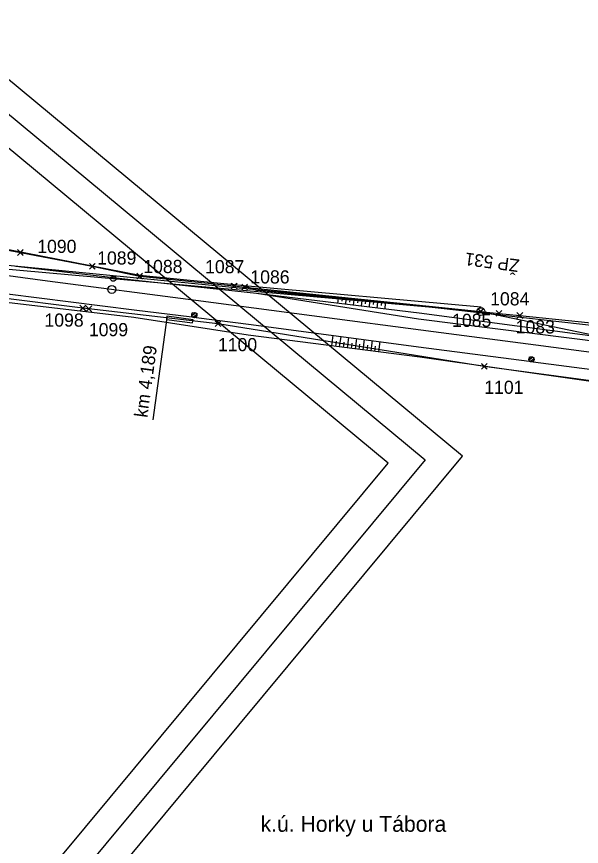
# Model space of a CAD drawing. Extents: x -738085 to -734426, y -1122197 to -1119748.
# Drawn here: x -737308.7 to -737201.5, y -1121531.4 to -1121373.8 of the extents above; entities that cross this region are included whole.
import ezdxf

# ---------------------------------------------------------------- set-up
doc = ezdxf.new("R2010")
doc.units = 0
for name, color, linetype in [('Polygon ku', 7, 'Continuous'), ('SŽDC', 7, 'Continuous'), ('Vrstva 1', 7, 'Continuous'), ('Vrstva 11', 7, 'Continuous'), ('Vrstva 12', 7, 'Continuous'), ('Vrstva 17', 7, 'Continuous'), ('Vrstva 48', 7, 'Continuous'), ('Vrstva 49', 7, 'Continuous'), ('Vrstva 60', 7, 'Continuous'), ('Vrstva 63', 7, 'Continuous'), ('Vrstva 7', 7, 'Continuous'), ('Vrstva 9', 7, 'Continuous')]:
    doc.layers.add(name, color=color, linetype=linetype)

msp = doc.modelspace()

# ---------------------------------------------------------------- linework, layer by layer
at = {"layer": 'SŽDC'}
for p, q in [((-737323.47, -1121415.6), (-737307.99, -1121418.58)), ((-737267.42, -1121424.92), (-737265.43, -1121425.13)), ((-737265.43, -1121425.13), (-737220.65, -1121429.77)), ((-737296.15, -1121429.13), (-737320.53, -1121426.11)), ((-737220.65, -1121429.77), (-737217.17, -1121430.13)), ((-737217.17, -1121430.13), (-737213.23, -1121430.54)), ((-737213.23, -1121430.54), (-737181.26, -1121433.89)), ((-737187.01, -1121444.71), (-737219.97, -1121440.21))]:
    msp.add_line(p, q, dxfattribs=at)
for points in [[(-737307.99, -1121418.58), (-737294.35, -1121421.2), (-737285.34, -1121423.08), (-737267.42, -1121424.92)], [(-737219.97, -1121440.21), (-737270.5, -1121432.11), (-737294.99, -1121429.27), (-737296.15, -1121429.13)]]:
    msp.add_lwpolyline(points, dxfattribs=at)
at = {"layer": 'Vrstva 1'}
for points in [[(-737452.56, -1121267.51), (-737989.34, -1121913.61), (-737760.91, -1122103.4), (-737224.12, -1121457.29)], [(-737982.3, -1121912.96), (-737451.91, -1121274.55), (-737231.17, -1121457.94), (-737761.56, -1122096.35)], [(-737451.26, -1121281.58), (-737844.27, -1121754.63), (-737631.21, -1121931.64), (-737238.2, -1121458.59)]]:
    msp.add_lwpolyline(points, close=True, dxfattribs=at)
msp.add_lwpolyline([(-737183.78, -1121439.67), (-737210.21, -1121436.2), (-737229.58, -1121433.65), (-737252.71, -1121430.59), (-737274.7, -1121427.68), (-737302.82, -1121423.99), (-737322.07, -1121421.44)], dxfattribs=at)
msp.add_lwpolyline([(-737183.78, -1121439.67), (-737210.21, -1121436.2), (-737229.58, -1121433.65), (-737252.71, -1121430.59), (-737274.7, -1121427.68), (-737302.82, -1121423.99), (-737322.07, -1121421.44)], dxfattribs=at)
at = {"layer": 'Vrstva 11'}
for p, q in [((-737274.72, -1121430.04), (-737275.46, -1121430.61)), ((-737274.5, -1121430.35), (-737275.22, -1121430.9)), ((-737210.75, -1121438.44), (-737211.49, -1121439.01)), ((-737210.53, -1121438.75), (-737211.26, -1121439.3))]:
    msp.add_line(p, q, dxfattribs=at)
for centre in [(-737274.98, -1121430.47), (-737211.01, -1121438.87)]:
    msp.add_circle(centre, 0.5, dxfattribs=at)
at = {"layer": 'Vrstva 12'}
for p, q in [((-737275.45, -1121430.82), (-737275.34, -1121430)), ((-737274.62, -1121430.93), (-737274.51, -1121430.11)), ((-737210.67, -1121439.32), (-737211.46, -1121439.21))]:
    msp.add_line(p, q, dxfattribs=at)
for points in [[(-737275.34, -1121430), (-737274.51, -1121430.11), (-737274.62, -1121430.93), (-737275.45, -1121430.82), (-737275.34, -1121430)], [(-737275.45, -1121430.82), (-737275.45, -1121430.82), (-737274.62, -1121430.93), (-737274.62, -1121430.93)], [(-737211.36, -1121438.42), (-737210.56, -1121438.52), (-737210.67, -1121439.32), (-737211.46, -1121439.21), (-737211.36, -1121438.42)], [(-737211.46, -1121439.21), (-737211.46, -1121439.21), (-737211.36, -1121438.42)], [(-737210.67, -1121439.32), (-737210.67, -1121439.32), (-737210.56, -1121438.52)]]:
    msp.add_lwpolyline(points, dxfattribs=at)
at = {"layer": 'Vrstva 17'}
msp.add_lwpolyline([(-737220.55, -1121428.94), (-737265.55, -1121424.89), (-737285.35, -1121422.95), (-737310.2, -1121418.09), (-737323.49, -1121415.48), (-737336.39, -1121414.26)], dxfattribs=at)
at = {"layer": 'Vrstva 48'}
for p, q in [((-737247.71, -1121427.28), (-737247.8, -1121428.23)), ((-737246.96, -1121427.35), (-737247.01, -1121427.83)), ((-737246.22, -1121427.42), (-737246.31, -1121428.41)), ((-737245.47, -1121427.5), (-737245.52, -1121428)), ((-737244.72, -1121427.57), (-737244.82, -1121428.59)), ((-737243.98, -1121427.64), (-737244.03, -1121428.16)), ((-737243.23, -1121427.71), (-737243.33, -1121428.77)), ((-737242.48, -1121427.78), (-737242.54, -1121428.32)), ((-737241.74, -1121427.86), (-737241.84, -1121428.95)), ((-737240.99, -1121427.93), (-737241.05, -1121428.48)), ((-737240.24, -1121428), (-737240.35, -1121429.13)), ((-737239.5, -1121428.07), (-737239.55, -1121428.65)), ((-737238.75, -1121428.14), (-737238.86, -1121429.31)), ((-737248.89, -1121436.3), (-737248.64, -1121434.3)), ((-737247.41, -1121436.49), (-737247.15, -1121434.5)), ((-737245.92, -1121436.68), (-737245.67, -1121434.7)), ((-737248.15, -1121436.4), (-737248.02, -1121435.4)), ((-737246.66, -1121436.59), (-737246.54, -1121435.59)), ((-737245.17, -1121436.78), (-737245.05, -1121435.79)), ((-737244.43, -1121436.87), (-737244.18, -1121434.9)), ((-737243.69, -1121436.97), (-737243.56, -1121435.98)), ((-737242.94, -1121437.06), (-737242.69, -1121435.1)), ((-737242.2, -1121437.16), (-737242.07, -1121436.18)), ((-737241.45, -1121437.25), (-737241.2, -1121435.3)), ((-737239.97, -1121437.44), (-737239.72, -1121435.5)), ((-737240.71, -1121437.35), (-737240.59, -1121436.37))]:
    msp.add_line(p, q, dxfattribs=at)
at = {"layer": 'Vrstva 49'}
msp.add_line((-737285.47, -1121423.95), (-737308.87, -1121421.25), dxfattribs=at)
for points in [[(-737285.35, -1121422.95), (-737310.2, -1121418.09), (-737316.73, -1121418.08), (-737334.06, -1121415.76)], [(-737080.08, -1121461.77), (-737090.67, -1121456.58), (-737111.11, -1121448.15), (-737130.72, -1121443.8), (-737153.05, -1121439.07), (-737181.79, -1121434.47), (-737232.07, -1121428.79), (-737263.11, -1121425.79), (-737265.55, -1121424.89), (-737285.35, -1121422.95)], [(-737042.34, -1121476.89), (-737045.96, -1121478.25), (-737051.31, -1121475.87), (-737059.65, -1121471.27), (-737080.08, -1121461.77), (-737095, -1121456.37), (-737113.75, -1121449.99), (-737130.88, -1121445.35), (-737152.07, -1121440.92), (-737182.74, -1121436.67), (-737232.31, -1121430.11), (-737263.17, -1121426.36), (-737285.47, -1121423.95)], [(-737310.42, -1121426.45), (-737286.42, -1121429.49), (-737275.45, -1121430.82), (-737274.62, -1121430.93), (-737264.2, -1121432.22), (-737232.43, -1121436.47), (-737211.46, -1121439.21), (-737210.67, -1121439.32), (-737183.93, -1121442.81), (-737153.07, -1121447.16), (-737152.28, -1121447.28), (-737151.31, -1121447.32), (-737132.33, -1121451.66), (-737115.31, -1121456.24), (-737098.74, -1121461.42), (-737083.52, -1121467.94), (-737082.8, -1121468.28), (-737082.23, -1121468.54), (-737062.89, -1121477.93), (-737046.92, -1121487.27), (-737045.25, -1121485.97)], [(-737044.27, -1121482.58), (-737060.3, -1121472.63), (-737080.61, -1121463.09), (-737095.26, -1121457.2), (-737114.01, -1121450.88), (-737131.11, -1121446.1), (-737152.37, -1121441.79), (-737182.77, -1121437.5), (-737232.42, -1121431.25), (-737263.17, -1121426.36)], [(-737045.25, -1121485.97), (-737046.65, -1121488.98), (-737063.8, -1121479.29), (-737083.11, -1121469.63), (-737099.88, -1121463.72), (-737115.42, -1121458.07), (-737133.05, -1121454.14), (-737151.03, -1121450.6), (-737184.2, -1121445.28), (-737232.18, -1121438.43), (-737264.79, -1121434.28), (-737286.45, -1121430.89), (-737310.61, -1121428.1)]]:
    msp.add_lwpolyline(points, dxfattribs=at)
at = {"layer": 'Vrstva 60'}
for p, q in [((-737307.54, -1121419.03), (-737308.54, -1121418.03)), ((-737307.54, -1121418.13), (-737308.54, -1121419.13)), ((-737308.44, -1121419.03), (-737307.44, -1121418.03)), ((-737308.44, -1121418.13), (-737307.44, -1121419.13)), ((-737307.99, -1121418.58), (-737307.99, -1121418.58)), ((-737293.9, -1121421.65), (-737294.9, -1121420.65)), ((-737293.9, -1121420.75), (-737294.9, -1121421.75)), ((-737294.8, -1121421.65), (-737293.8, -1121420.65)), ((-737294.8, -1121420.75), (-737293.8, -1121421.75)), ((-737294.35, -1121421.2), (-737294.35, -1121421.2)), ((-737284.89, -1121423.53), (-737285.89, -1121422.53)), ((-737284.89, -1121422.63), (-737285.89, -1121423.63)), ((-737285.79, -1121423.53), (-737284.79, -1121422.53)), ((-737285.79, -1121422.63), (-737284.79, -1121423.63)), ((-737285.34, -1121423.08), (-737285.34, -1121423.08)), ((-737266.97, -1121425.37), (-737267.97, -1121424.37)), ((-737266.97, -1121424.47), (-737267.97, -1121425.47)), ((-737267.87, -1121425.37), (-737266.87, -1121424.37)), ((-737267.87, -1121424.47), (-737266.87, -1121425.47)), ((-737267.42, -1121424.92), (-737267.42, -1121424.92)), ((-737264.98, -1121425.58), (-737265.98, -1121424.58)), ((-737264.98, -1121424.68), (-737265.98, -1121425.68)), ((-737265.88, -1121425.58), (-737264.88, -1121424.58)), ((-737265.88, -1121424.68), (-737264.88, -1121425.68)), ((-737265.43, -1121425.13), (-737265.43, -1121425.13)), ((-737295.7, -1121429.58), (-737296.7, -1121428.58)), ((-737295.7, -1121428.68), (-737296.7, -1121429.68)), ((-737296.6, -1121429.58), (-737295.6, -1121428.58)), ((-737296.6, -1121428.68), (-737295.6, -1121429.68)), ((-737296.15, -1121429.13), (-737296.15, -1121429.13)), ((-737294.54, -1121429.72), (-737295.54, -1121428.72)), ((-737294.54, -1121428.82), (-737295.54, -1121429.82)), ((-737295.44, -1121429.72), (-737294.44, -1121428.72)), ((-737295.44, -1121428.82), (-737294.44, -1121429.82)), ((-737294.99, -1121429.27), (-737294.99, -1121429.27)), ((-737220.2, -1121430.22), (-737221.2, -1121429.22)), ((-737220.2, -1121429.32), (-737221.2, -1121430.32)), ((-737221.1, -1121430.22), (-737220.1, -1121429.22)), ((-737221.1, -1121429.32), (-737220.1, -1121430.32)), ((-737220.65, -1121429.77), (-737220.65, -1121429.77)), ((-737216.72, -1121430.58), (-737217.72, -1121429.58)), ((-737216.72, -1121429.68), (-737217.72, -1121430.68)), ((-737217.62, -1121430.58), (-737216.62, -1121429.58)), ((-737217.62, -1121429.68), (-737216.62, -1121430.68)), ((-737212.78, -1121430.99), (-737213.78, -1121429.99)), ((-737213.68, -1121430.99), (-737212.68, -1121429.99)), ((-737270.05, -1121432.56), (-737271.05, -1121431.56)), ((-737270.95, -1121432.56), (-737269.95, -1121431.56)), ((-737217.17, -1121430.13), (-737217.17, -1121430.13)), ((-737212.78, -1121430.09), (-737213.78, -1121431.09)), ((-737213.68, -1121430.09), (-737212.68, -1121431.09)), ((-737213.23, -1121430.54), (-737213.23, -1121430.54)), ((-737270.05, -1121431.66), (-737271.05, -1121432.66)), ((-737270.95, -1121431.66), (-737269.95, -1121432.66)), ((-737270.5, -1121432.11), (-737270.5, -1121432.11)), ((-737219.52, -1121440.66), (-737220.52, -1121439.66)), ((-737219.52, -1121439.76), (-737220.52, -1121440.76)), ((-737220.42, -1121440.66), (-737219.42, -1121439.66)), ((-737220.42, -1121439.76), (-737219.42, -1121440.76)), ((-737219.97, -1121440.21), (-737219.97, -1121440.21))]:
    msp.add_line(p, q, dxfattribs=at)
at = {"layer": 'Vrstva 63'}
for p, q in [((-737376.13, -1121415.82), (-737220.61, -1121429.81)), ((-737364.62, -1121415.63), (-737220.61, -1121429.81)), ((-737220.56, -1121429.82), (-737220.66, -1121429.81)), ((-737220.61, -1121429.81), (-737099.21, -1121455.15))]:
    msp.add_line(p, q, dxfattribs=at)
msp.add_circle((-737220.61, -1121429.81), 0.756, dxfattribs=at)
at = {"layer": 'Vrstva 7'}
msp.add_line((-737290.32, -1121423.56), (-737290.42, -1121423.55), dxfattribs=at)
for centre, radius in [((-737290.37, -1121423.55), 0.5), ((-737290.64, -1121425.59), 0.75), ((-737290.64, -1121425.59), 0.75)]:
    msp.add_circle(centre, radius, dxfattribs=at)
at = {"layer": 'Vrstva 9'}
for p, q in [((-737280.23, -1121430.99), (-737282.85, -1121450.34)), ((-737280.27, -1121431.29), (-737280.35, -1121431.88)), ((-737280.19, -1121430.69), (-737280.27, -1121431.29)), ((-737280.27, -1121431.29), (-737275.31, -1121431.94)), ((-737275.23, -1121431.34), (-737280.19, -1121430.69)), ((-737275.31, -1121431.94), (-737275.23, -1121431.34))]:
    msp.add_line(p, q, dxfattribs=at)

# ---------------------------------------------------------------- texts
at = {"layer": 'Polygon ku'}
msp.add_text('k.ú. Horky u Tábora', height=3, dxfattribs=at).set_placement((-737262.41, -1121528.61))
at = {"layer": 'Vrstva 60'}
for s, p in [('1090', (-737304.79, -1121418.66)), ('1089', (-737293.42, -1121420.86)), ('1088', (-737284.67, -1121422.48)), ('1087', (-737272.94, -1121422.52)), ('1086', (-737264.35, -1121424.46)), ('1084', (-737218.85, -1121428.62)), ('1098', (-737303.42, -1121432.66)), ('1085', (-737226.07, -1121432.71)), ('1083', (-737214, -1121433.95)), ('1099', (-737294.99, -1121434.48)), ('1100', (-737270.5, -1121437.32)), ('1101', (-737219.97, -1121445.42))]:
    msp.add_text(s, height=2.5, dxfattribs=at).set_placement(p)
at = {"layer": 'Vrstva 63'}
msp.add_text('ŽP 531', height=2.4, rotation=172.4873, dxfattribs=at).set_placement((-737213.2, -1121419.93))
at = {"layer": 'Vrstva 9'}
msp.add_text('km 4,189', height=2.5, rotation=82.2895, dxfattribs=at).set_placement((-737283.91, -1121450.03))

doc.saveas('drawing.dxf')
